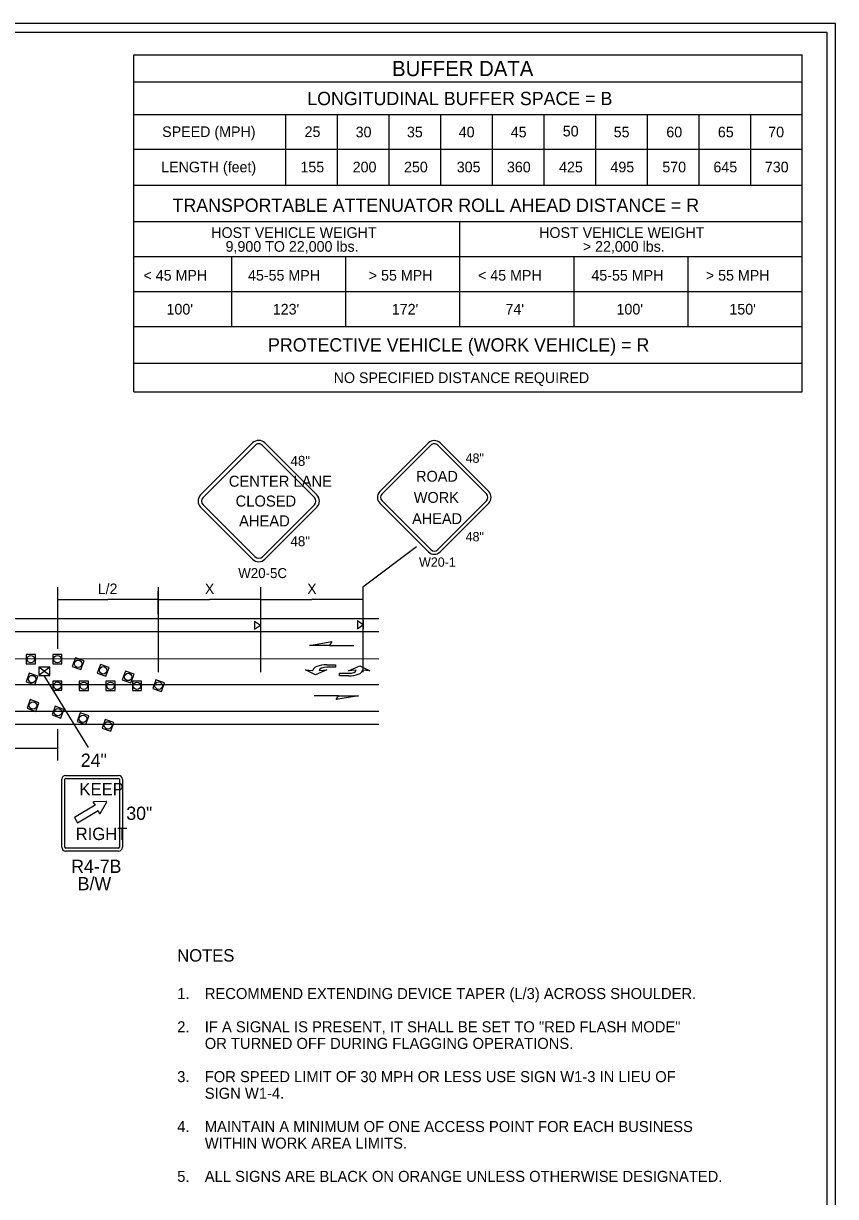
# Model space of a CAD drawing. Extents: x 99988 to 100172, y 99995 to 100047.
# Drawn here: x 100009.92 to 100015.81, y 100001.92 to 100010.44 of the extents above; entities that cross this region are included whole.
import ezdxf

# ---------------------------------------------------------------- set-up
doc = ezdxf.new("R2010")
doc.units = 0
for name, color, linetype in [('Default', 7, 'Continuous'), ('Level 15', 7, 'Continuous'), ('Level 20', 7, 'Continuous'), ('RD_MK_TrafficArrowType2LNew', 7, 'Continuous'), ('SH_GI_PlotLimits', 7, 'Continuous'), ('SH_GI_SheetBorder', 7, 'Continuous'), ('SH_GI_TrafficMvmntArrowRt1Lane', 7, 'Continuous'), ('SH_TI_BufferDataNote', 7, 'Continuous'), ('TR_SN_WarningSigns', 7, 'Continuous'), ('TR_WZ_TrafficSafetyCone', 7, 'Continuous'), ('TR_WZ_TruckBuffer', 7, 'Continuous'), ('TR_WZ_WorkZoneDetails', 7, 'Continuous')]:
    doc.layers.add(name, color=color, linetype=linetype)

msp = doc.modelspace()

# ---------------------------------------------------------------- linework, layer by layer
at = {"layer": 'Default'}
for p, q in [((100011.5964, 100006.0998), (100011.6388, 100006.0703)), ((100011.5964, 100006.0998), (100011.5964, 100006.0408)), ((100011.6388, 100006.0998), (100011.6388, 100006.0408)), ((100012.3429, 100006.1031), (100012.3852, 100006.0737)), ((100012.3429, 100006.1031), (100012.3429, 100006.0441)), ((100012.3852, 100006.1031), (100012.3852, 100006.0441)), ((100011.5964, 100006.0408), (100011.6388, 100006.0703)), ((100012.3429, 100006.0441), (100012.3852, 100006.0737)), ((100012.4977, 100005.8223), (100007.1718, 100005.8262)), ((100010.1103, 100005.7052), (100010.0304, 100005.765)), ((100010.1103, 100005.765), (100010.0304, 100005.7052)), ((100010.0704, 100005.7351), (100010.0704, 100005.7351)), ((100010.0705, 100005.735), (100010.0705, 100005.735))]:
    msp.add_line(p, q, dxfattribs=at)
msp.add_lwpolyline([(100010.1103, 100005.7052), (100010.1103, 100005.765), (100010.0304, 100005.765), (100010.0304, 100005.7052)], close=True, dxfattribs=at)
at = {"layer": 'Level 15'}
for p, q in [((100010.1648, 100006.2567), (100010.5307, 100006.2567)), ((100010.8967, 100006.2567), (100010.5307, 100006.2567)), ((100010.8967, 100006.2567), (100011.2679, 100006.2567)), ((100011.6392, 100006.2567), (100011.2679, 100006.2567)), ((100011.6392, 100006.2567), (100012.0104, 100006.2567)), ((100012.3817, 100006.2567), (100012.0104, 100006.2567)), ((100010.1648, 100005.1739), (100009.7943, 100005.1739))]:
    msp.add_line(p, q, dxfattribs=at)
at = {"layer": 'RD_MK_TrafficArrowType2LNew'}
for p, q in [((100012.1202, 100005.7824), (100012.1202, 100005.7824)), ((100012.1202, 100005.7824), (100012.1202, 100005.7824)), ((100012.1202, 100005.764), (100012.1202, 100005.764)), ((100012.0194, 100005.7411), (100012.0194, 100005.7411)), ((100012.0652, 100005.7411), (100012.0652, 100005.7411)), ((100012.2774, 100005.7023), (100012.2774, 100005.7023)), ((100012.2774, 100005.7023), (100012.2774, 100005.7023)), ((100012.2775, 100005.7206), (100012.2775, 100005.7206)), ((100012.3328, 100005.7429), (100012.3328, 100005.7429)), ((100012.3786, 100005.7425), (100012.3786, 100005.7425))]:
    msp.add_line(p, q, dxfattribs=at)
for points in [[(100012.0652, 100005.7411), (100012.1202, 100005.7457), (100012.0377, 100005.709), (100011.9644, 100005.7457), (100012.0194, 100005.7411)], [(100012.1202, 100005.7824), (100012.1844, 100005.7824), (100012.1844, 100005.764), (100012.1202, 100005.764)], [(100012.3328, 100005.7429), (100012.2777, 100005.7389), (100012.3606, 100005.7748), (100012.4336, 100005.7374), (100012.3786, 100005.7425)], [(100012.2774, 100005.7023), (100012.2132, 100005.7029), (100012.2134, 100005.7212), (100012.2775, 100005.7206)]]:
    msp.add_lwpolyline(points, dxfattribs=at)
for centre, major_axis, ratio, start_param in [((100012.1202, 100005.7411), (-0.1008, 0), 0.40879, 4.712524), ((100012.1202, 100005.7411), (-0.055, 0), 0.41611, 4.712518), ((100012.2778, 100005.7435), (0.1008, -0.001), 0.40879, 4.712524), ((100012.2778, 100005.7435), (0.055, -0.0006), 0.41611, 4.712518)]:
    msp.add_ellipse(centre, major_axis=major_axis, ratio=ratio, start_param=start_param, end_param=6.283185, dxfattribs=at)
at = {"layer": 'SH_GI_PlotLimits'}
msp.add_lwpolyline([(99999.3125, 99999.9375), (100015.8125, 99999.9375), (100015.8125, 100010.4375), (99999.3125, 100010.4375)], close=True, dxfattribs=at)
at = {"layer": 'SH_GI_SheetBorder'}
for p, q in [((100000, 100010.375), (100015.75, 100010.375)), ((100015.75, 100010.375), (100015.75, 100000))]:
    msp.add_line(p, q, dxfattribs=at)
at = {"layer": 'SH_GI_TrafficMvmntArrowRt1Lane'}
for p, q in [((100012.1394, 100005.9228), (100012.3163, 100005.9228)), ((100012.2055, 100005.5577), (100012.0287, 100005.5577))]:
    msp.add_line(p, q, dxfattribs=at)
for points in [[(100011.9953, 100005.9228), (100012.1558, 100005.9511), (100012.1394, 100005.9228)], [(100012.3496, 100005.5577), (100012.1892, 100005.5294), (100012.2055, 100005.5577)]]:
    msp.add_lwpolyline(points, close=True, dxfattribs=at)
at = {"layer": 'SH_TI_BufferDataNote'}
for p, q in [((100010.7191, 100010.2101), (100015.5705, 100010.2101)), ((100010.7191, 100008.2375), (100010.7191, 100010.2101)), ((100015.5705, 100007.7628), (100015.5705, 100010.2101)), ((100010.7191, 100010.0127), (100015.5705, 100010.0127)), ((100010.7191, 100009.7761), (100015.5705, 100009.7761)), ((100011.8215, 100009.7761), (100011.8215, 100009.2634)), ((100012.1964, 100009.7761), (100012.1964, 100009.2634)), ((100012.5713, 100009.7761), (100012.5713, 100009.2634)), ((100012.9462, 100009.7761), (100012.9462, 100009.2634)), ((100013.3211, 100009.7761), (100013.3211, 100009.2634)), ((100013.696, 100009.7761), (100013.696, 100009.2634)), ((100014.0709, 100009.7761), (100014.0709, 100009.2634)), ((100014.4458, 100009.7761), (100014.4458, 100009.2634)), ((100014.8207, 100009.7761), (100014.8207, 100009.2634)), ((100015.1956, 100009.7761), (100015.1956, 100009.2634)), ((100010.7191, 100009.5257), (100015.5705, 100009.5257)), ((100010.7191, 100009.2634), (100015.5705, 100009.2634)), ((100010.7191, 100008.9992), (100015.5705, 100008.9992)), ((100013.0865, 100008.2375), (100013.0865, 100008.9971)), ((100010.7191, 100008.7453), (100015.5705, 100008.7453)), ((100010.7191, 100007.7628), (100010.7191, 100008.7453)), ((100011.4307, 100008.2375), (100011.4307, 100008.7453)), ((100012.2587, 100008.2375), (100012.2587, 100008.7453)), ((100013.0867, 100008.2375), (100013.0867, 100008.7453)), ((100013.9147, 100008.2375), (100013.9147, 100008.7453)), ((100014.7427, 100008.2375), (100014.7427, 100008.7453)), ((100010.7191, 100008.4914), (100015.5705, 100008.4914)), ((100010.7191, 100008.2375), (100015.5705, 100008.2375)), ((100010.7191, 100007.9725), (100015.5705, 100007.9725)), ((100010.7191, 100007.7628), (100015.5705, 100007.7628))]:
    msp.add_line(p, q, dxfattribs=at)
at = {"layer": 'TR_SN_WarningSigns'}
for p, q in [((100011.2043, 100007.0156), (100011.5812, 100007.3925)), ((100011.2222, 100006.9977), (100011.5992, 100007.3746)), ((100011.653, 100007.3746), (100012.03, 100006.9977)), ((100011.671, 100007.3925), (100012.0479, 100007.0156)), ((100012.5045, 100007.0392), (100012.8579, 100007.3925)), ((100012.5213, 100007.0223), (100012.8747, 100007.3757)), ((100012.9252, 100007.3757), (100013.2786, 100007.0223)), ((100012.942, 100007.3925), (100013.2954, 100007.0392)), ((100011.5992, 100006.5669), (100011.2222, 100006.9438)), ((100012.03, 100006.9438), (100011.653, 100006.5669)), ((100012.8579, 100006.6016), (100012.5045, 100006.955)), ((100012.8747, 100006.6185), (100012.5213, 100006.9718)), ((100013.2785, 100006.9718), (100012.9252, 100006.6185)), ((100013.2954, 100006.955), (100012.942, 100006.6016)), ((100011.5812, 100006.5489), (100011.2043, 100006.9259)), ((100012.0479, 100006.9259), (100011.671, 100006.5489))]:
    msp.add_line(p, q, dxfattribs=at)
for centre, radius, start, end in [((100011.6261, 100007.3477), 0.0635, 44.99628, 134.99965), ((100011.6261, 100007.3477), 0.0381, 44.99628, 134.99965), ((100012.8999, 100007.3505), 0.0595, 44.99628, 134.99965), ((100012.8999, 100007.3505), 0.0357, 44.99628, 134.99965), ((100012.5465, 100006.9971), 0.0595, 134.99658, 224.99358), ((100013.2533, 100006.9971), 0.0595, 314.99936, 44.99485), ((100011.2491, 100006.9707), 0.0635, 134.99658, 224.99358), ((100011.2491, 100006.9707), 0.0381, 134.99658, 224.99358), ((100012.003, 100006.9707), 0.0381, 314.99936, 44.99485), ((100012.003, 100006.9707), 0.0635, 314.99936, 44.99485), ((100012.5465, 100006.9971), 0.0357, 134.99658, 224.99358), ((100013.2533, 100006.9971), 0.0357, 314.99936, 44.99485), ((100012.8999, 100006.6437), 0.0595, 225, 314.99958), ((100012.8999, 100006.6437), 0.0357, 225, 314.99958), ((100011.6261, 100006.5938), 0.0635, 225, 314.99958), ((100011.6261, 100006.5938), 0.0381, 225, 314.99958)]:
    msp.add_arc(centre, radius, start, end, dxfattribs=at)
at = {"layer": 'TR_WZ_TrafficSafetyCone'}
for points in [[(100009.9389, 100005.7894), (100010.0057, 100005.7894), (100010.0057, 100005.8562), (100009.9389, 100005.8562)], [(100010.1314, 100005.7894), (100010.1982, 100005.7894), (100010.1982, 100005.8562), (100010.1314, 100005.8562)], [(100010.2731, 100005.7701), (100010.3359, 100005.7472), (100010.3587, 100005.81), (100010.296, 100005.8328)], [(100010.4546, 100005.722), (100010.5174, 100005.6992), (100010.5402, 100005.762), (100010.4775, 100005.7848)], [(100009.9383, 100005.6588), (100010.001, 100005.636), (100010.0239, 100005.6987), (100009.9611, 100005.7216)], [(100010.1314, 100005.5973), (100010.1982, 100005.5973), (100010.1982, 100005.6641), (100010.1314, 100005.6641)], [(100010.3239, 100005.5968), (100010.3907, 100005.5968), (100010.3907, 100005.6636), (100010.3239, 100005.6636)], [(100010.5164, 100005.5963), (100010.5832, 100005.5963), (100010.5832, 100005.6631), (100010.5164, 100005.6631)], [(100010.6361, 100005.674), (100010.6989, 100005.6512), (100010.7217, 100005.7139), (100010.659, 100005.7368)], [(100010.7089, 100005.5958), (100010.7757, 100005.5958), (100010.7757, 100005.6626), (100010.7089, 100005.6626)], [(100010.8569, 100005.6108), (100010.9197, 100005.5879), (100010.9425, 100005.6507), (100010.8797, 100005.6736)], [(100009.9449, 100005.4667), (100010.0077, 100005.4439), (100010.0306, 100005.5066), (100009.9678, 100005.5295)], [(100010.1264, 100005.4187), (100010.1892, 100005.3958), (100010.2121, 100005.4586), (100010.1493, 100005.4815)], [(100010.3079, 100005.3707), (100010.3707, 100005.3478), (100010.3936, 100005.4106), (100010.3308, 100005.4334)], [(100010.4894, 100005.3227), (100010.5522, 100005.2998), (100010.5751, 100005.3626), (100010.5123, 100005.3854)]]:
    msp.add_lwpolyline(points, close=True, dxfattribs=at)
for centre in [(100009.9723, 100005.8228), (100010.1648, 100005.8228), (100010.3159, 100005.79), (100010.4974, 100005.742), (100009.9811, 100005.6788), (100010.6789, 100005.694), (100010.1648, 100005.6307), (100010.3573, 100005.6302), (100010.5498, 100005.6297), (100010.7423, 100005.6292), (100010.8997, 100005.6307), (100009.9877, 100005.4867), (100010.1692, 100005.4387), (100010.3507, 100005.3906), (100010.5322, 100005.3426)]:
    msp.add_circle(centre, 0.0268, dxfattribs=at)
at = {"layer": 'TR_WZ_TruckBuffer'}
for p, q in [((100010.2237, 100004.9795), (100010.6088, 100004.9795)), ((100010.1962, 100004.4582), (100010.1962, 100004.9509)), ((100010.2179, 100004.4582), (100010.2179, 100004.9509)), ((100010.2237, 100004.957), (100010.6088, 100004.957)), ((100010.6146, 100004.9509), (100010.6146, 100004.4582)), ((100010.6362, 100004.9509), (100010.6362, 100004.4582)), ((100010.4393, 100004.7645), (100010.2897, 100004.6746)), ((100010.3119, 100004.6346), (100010.4614, 100004.7245)), ((100010.4258, 100004.7793), (100010.4393, 100004.7645)), ((100010.5175, 100004.7899), (100010.4294, 100004.7881)), ((100010.4614, 100004.7245), (100010.4669, 100004.7049)), ((100010.4761, 100004.7036), (100010.5219, 100004.7819)), ((100010.2897, 100004.6746), (100010.3119, 100004.6346)), ((100010.6088, 100004.4521), (100010.2237, 100004.4521)), ((100010.6088, 100004.4295), (100010.2237, 100004.4295))]:
    msp.add_line(p, q, dxfattribs=at)
for centre, major_axis, ratio, start_param, end_param in [((100010.2237, 100004.9509), (0, -0.0286), 0.960021, 3.141593, 4.712389), ((100010.6088, 100004.9509), (0, 0.0286), 0.960021, 4.712389, 6.283185), ((100010.2237, 100004.9509), (0, -0.00611), 0.960051, 3.141593, 4.712389), ((100010.6088, 100004.9509), (0, 0.00611), 0.960051, 4.712389, 6.283185), ((100010.4295, 100004.7829), (0, 0.00526), 0.96, 0.019017, 2.328605), ((100010.5176, 100004.7846), (0, -0.00526), 0.96, 1.023619, 3.16061), ((100010.4718, 100004.7064), (0, -0.00526), 0.96, 4.99813, 7.306805), ((100010.2237, 100004.4582), (0, -0.0286), 0.960021, 4.712389, 6.283185), ((100010.2237, 100004.4582), (0, -0.00611), 0.960051, 4.712389, 6.283185), ((100010.6088, 100004.4582), (0, -0.00611), 0.960051, 0, 1.570796), ((100010.6088, 100004.4582), (0, -0.0286), 0.960021, 0, 1.570796)]:
    msp.add_ellipse(centre, major_axis=major_axis, ratio=ratio, start_param=start_param, end_param=end_param, dxfattribs=at)
at = {"layer": 'TR_WZ_WorkZoneDetails'}
for p, q in [((100012.7702, 100006.6394), (100012.3817, 100006.3447)), ((100010.1648, 100006.3447), (100010.1648, 100005.8988)), ((100010.8967, 100006.3447), (100010.8967, 100005.7285)), ((100011.6392, 100006.3447), (100011.6392, 100005.7285)), ((100012.3817, 100006.3447), (100012.3817, 100005.7285)), ((100010.8967, 100006.1527), (100010.8967, 100006.3174)), ((100009.3032, 100006.1188), (100012.4976, 100006.1188)), ((100009.3032, 100006.0227), (100012.4976, 100006.0227)), ((100010.3903, 100005.1811), (100010.0694, 100005.7055)), ((100008.0804, 100005.6386), (100012.4976, 100005.6386)), ((100009.3032, 100005.4465), (100012.4976, 100005.4465)), ((100009.3032, 100005.3505), (100012.4976, 100005.3505)), ((100010.1648, 100005.3139), (100010.1648, 100005.0864))]:
    msp.add_line(p, q, dxfattribs=at)

# ---------------------------------------------------------------- texts
at = {"layer": 'Level 20'}
for s, p in [('L/2', (100010.4574, 100006.2952)), ('X', (100011.2352, 100006.2952)), ('X', (100011.9777, 100006.2952))]:
    msp.add_text(s, height=0.077, rotation=360, dxfattribs=at).set_placement(p)
for s, height, p in [('NOTES', 0.09, (100011.0345, 100003.6279)), ('1.', 0.08, (100011.0345, 100003.3559)), ('RECOMMEND EXTENDING DEVICE TAPER (L/3) ACROSS SHOULDER.', 0.08, (100011.2345, 100003.3559)), ('2.', 0.08, (100011.0345, 100003.1146)), ('IF A SIGNAL IS PRESENT, IT SHALL BE SET TO "RED FLASH MODE"', 0.08, (100011.2345, 100003.1146)), ('OR TURNED OFF DURING FLAGGING OPERATIONS.', 0.08, (100011.2345, 100002.9939)), ('3.', 0.08, (100011.0345, 100002.7527)), ('FOR SPEED LIMIT OF 30 MPH OR LESS USE SIGN W1-3 IN LIEU OF', 0.08, (100011.2345, 100002.7527)), ('SIGN W1-4.', 0.08, (100011.2345, 100002.632)), ('4.', 0.08, (100011.0345, 100002.3907)), ('MAINTAIN A MINIMUM OF ONE ACCESS POINT FOR EACH BUSINESS', 0.08, (100011.2345, 100002.3907)), ('WITHIN WORK AREA LIMITS.', 0.08, (100011.2345, 100002.2701)), ('5.', 0.08, (100011.0345, 100002.0288)), ('ALL SIGNS ARE BLACK ON ORANGE UNLESS OTHERWISE DESIGNATED.', 0.08, (100011.2345, 100002.0288))]:
    msp.add_text(s, height=height, dxfattribs=at).set_placement(p)
at = {"layer": 'SH_TI_BufferDataNote'}
for s, height, p in [('BUFFER DATA', 0.1104, (100012.5939, 100010.0551)), ('LONGITUDINAL BUFFER SPACE = B', 0.0966, (100011.9783, 100009.8445)), ('SPEED (MPH)', 0.07728, (100010.9253, 100009.6131)), ('25', 0.07728, (100011.9591, 100009.6131)), ('30', 0.07728, (100012.3295, 100009.6109)), ('35', 0.07728, (100012.7018, 100009.6109)), ('40', 0.07728, (100013.0779, 100009.6109)), ('45', 0.07728, (100013.4553, 100009.6109)), ('50', 0.07728, (100013.8327, 100009.6175)), ('55', 0.07728, (100014.2023, 100009.6109)), ('60', 0.07728, (100014.5845, 100009.6109)), ('65', 0.07728, (100014.9585, 100009.6109)), ('70', 0.07728, (100015.3242, 100009.6109)), ('LENGTH (feet)', 0.07728, (100010.9183, 100009.3568)), ('155', 0.07728, (100011.9287, 100009.3568)), ('200', 0.07728, (100012.308, 100009.3568)), ('250', 0.07728, (100012.6805, 100009.3568)), ('305', 0.07728, (100013.0633, 100009.3568)), ('360', 0.07728, (100013.4275, 100009.3568)), ('425', 0.07728, (100013.8058, 100009.3568)), ('495', 0.07728, (100014.1786, 100009.3568)), ('570', 0.07728, (100014.5553, 100009.3568)), ('645', 0.07728, (100014.9264, 100009.3568)), ('730', 0.07728, (100015.2996, 100009.3568)), ('TRANSPORTABLE ATTENUATOR ROLL AHEAD DISTANCE = R', 0.0966, (100011.0004, 100009.0699)), ('HOST VEHICLE WEIGHT', 0.07728, (100011.2815, 100008.8809)), ('HOST VEHICLE WEIGHT', 0.07728, (100013.6613, 100008.8809)), ('9,900 TO 22,000 lbs.', 0.07728, (100011.3854, 100008.7803)), ('> 22,000 lbs.', 0.07728, (100013.9782, 100008.7803)), ('< 45 MPH', 0.07728, (100010.7896, 100008.5707)), ('45-55 MPH', 0.07728, (100011.5483, 100008.5707)), ('> 55 MPH', 0.07728, (100012.4247, 100008.5707)), ('< 45 MPH', 0.07728, (100013.2178, 100008.5707)), ('45-55 MPH', 0.07728, (100014.0405, 100008.5707)), ('> 55 MPH', 0.07728, (100014.8713, 100008.5707)), ("100'", 0.07728, (100010.9569, 100008.3248)), ("123'", 0.07728, (100011.7283, 100008.3248)), ("172'", 0.07728, (100012.592, 100008.3248)), ("74'", 0.07728, (100013.4169, 100008.3248)), ("100'", 0.07728, (100014.223, 100008.3248)), ("150'", 0.07728, (100015.0421, 100008.3248)), ('PROTECTIVE VEHICLE (WORK VEHICLE) = R', 0.0966, (100011.6936, 100008.0562)), ('NO SPECIFIED DISTANCE REQUIRED', 0.07728, (100012.17, 100007.8273))]:
    msp.add_text(s, height=height, dxfattribs=at).set_placement(p)
at = {"layer": 'TR_SN_WarningSigns'}
for s, height, p in [('48"', 0.07219, (100011.8567, 100007.2263)), ('48"', 0.06768, (100013.1277, 100007.2483)), ('CENTER LANE', 0.079952, (100011.409, 100007.0747)), ('ROAD', 0.0787, (100012.7675, 100007.1114)), ('WORK', 0.0787, (100012.7513, 100006.9578)), ('CLOSED', 0.07995, (100011.4584, 100006.9308)), ('AHEAD', 0.07995, (100011.4834, 100006.7868)), ('AHEAD', 0.0787, (100012.7394, 100006.8041)), ('48"', 0.07219, (100011.8567, 100006.643)), ('48"', 0.06768, (100013.1277, 100006.6782)), ('W20-1', 0.06768, (100012.7898, 100006.4938)), ('W20-5C', 0.07219, (100011.4774, 100006.4117))]:
    msp.add_text(s, height=height, dxfattribs=at).set_placement(p)
at = {"layer": 'TR_WZ_TruckBuffer'}
for s, height, p in [('24"', 0.09625, (100010.3348, 100005.0414)), ('KEEP', 0.09016, (100010.3249, 100004.835)), ('30"', 0.09625, (100010.6648, 100004.6564)), ('RIGHT', 0.09016, (100010.2974, 100004.5101)), ('R4-7B', 0.09625, (100010.2648, 100004.2714)), ('B/W', 0.09625, (100010.3121, 100004.1454))]:
    msp.add_text(s, height=height, dxfattribs=at).set_placement(p)

doc.saveas('drawing.dxf')
